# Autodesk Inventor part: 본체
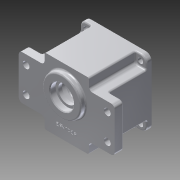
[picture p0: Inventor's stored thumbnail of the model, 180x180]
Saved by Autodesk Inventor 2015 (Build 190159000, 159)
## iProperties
Created: 2014-12
Part Number: 본체
Material: 알루미늄 6061
Document SubType Name: Modeling
Designer: 영환
Density: 2.7 g/cm^3
Appearance: 알루미늄 - 평지
Mass: 705.786 g
Surface Area: 673.294 cm^2
Volume: 261.402 cm^3
Author: 영환
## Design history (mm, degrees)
node "작업 평면1"
sketch "스케치1"
  geometry: L1 (45, -45)-(-45, -45); L2 (-45, -45)-(-45, 45); L3 (-45, 45)-(45, 45); L4 (45, 45)-(45, -45); L5 (45, -45)-(-45, 45); L6 (-45, -45)-(45, 45); 1 further point
  constraints: 12 end point, 2 midpoint, 2 parallel, 1 horizontal, 1 perpendicular
  dimensions: "d0" = 90 distance of L2.end L3.end; "d1" = 90 distance of L1.end L2.end
extrude "돌출1" new body sketch "스케치1" distance "d3" = 70; taper "d4" = 0 deg
sketch "스케치2"
  geometry: L1 (-65, 30)-(65, 30); L2 (65, 30)-(65, -30); L3 (65, -30)-(-65, -30); L4 (-65, -30)-(-65, 30); L5 (-65, 30)-(65, -30); L6 (65, 30)-(-65, -30); 1 further point
  constraints: 12 end point, 2 midpoint, 2 parallel, 1 horizontal, 1 perpendicular
  dimensions: "d5" = 130 distance of L2.end L3.end; "d6" = 60 distance of L1.end L2.end
extrude "돌출2" join sketch "스케치2" distance "d7" = 12; taper "d8" = 0 deg
sketch "스케치3"
  geometry: L1 (-45, -45)-(45, -45) reference; L2 (45, -45)-(45, -30) reference; L3 (45, 45)-(-45, 45) reference; L4 (-45, 45)-(-45, 30) reference; L5 (45, 45)-(30, 45); L6 (30, 45)-(30, 30); L7 (30, 30)-(45, 30); L8 (45, 30)-(45, 45); L9 (-45, 45)-(-45, 30); L10 (-45, 30)-(-30, 30); L11 (-30, 30)-(-30, 45); L12 (-30, 45)-(-45, 45); L13 (-45, -45)-(-30, -45); L14 (-30, -45)-(-30, -30); L15 (-30, -30)-(-45, -30); L16 (-45, -30)-(-45, -45); L17 (45, -45)-(45, -30); L18 (45, -30)-(30, -30); L19 (30, -30)-(30, -45); L20 (30, -45)-(45, -45); L21 (-45, -30)-(-45, -45) reference; L22 (65, -30)-(45, -30) reference; L23 (65, 30)-(65, -30) reference; L24 (45, 30)-(65, 30) reference; L25 (45, 30)-(45, 45) reference; L26 (-65, 30)-(-45, 30) reference; L27 (-65, -30)-(-65, 30) reference; L28 (-45, -30)-(-65, -30) reference; 1 further point
  constraints: 32 end point, 2 parallel, 1 horizontal, 1 perpendicular, 33 other
  dimensions: "d9" = 15 distance between parallel lines of L2 L6; "d10" = 15 distance of L5.end L6.end; "d13" = 360 deg dimension on point (0, 0) L6.end (derived)
extrude "돌출3" cut sketch "스케치3" distance "d15" = 63; taper "d16" = 0 deg
sketch "스케치4"
  geometry: 2 further points
  constraints: 1 coincident
hole "구멍1" sketch "스케치4" at (0, 0) diameter "d17" = 78; stored, may be unused: countersink angle "d21" = 90 deg, drill point angle "d23" = 0 deg; dims "d18" = 6, "d19" = 80, "d20" = 9, "d22" = 61
sketch "스케치5"
  geometry: L1 (-27.577, 21.92)-(-30.26, 24.603); L2 (-21.92, 27.577)-(-24.603, 30.26); L3 (-27.577, -21.92)-(-30.26, -24.603); L4 (-21.92, -27.577)-(-24.603, -30.26); L5 (21.92, -27.577)-(24.603, -30.26); L6 (27.577, -21.92)-(30.26, -24.603); L7 (27.577, 21.92)-(30.26, 24.603); L8 (21.92, 27.577)-(24.603, 30.26); C1 r 35 at (0, 0); A1 r 4 centre (-24.749, 24.749) between (-27.577, 21.92) and (-21.92, 27.577); A2 r 39 centre (0, 0) between (-24.603, 30.26) and (-30.26, 24.603); A3 r 4 centre (-24.749, -24.749) between (-21.92, -27.577) and (-27.577, -21.92); A4 r 39 centre (0, 0) between (-30.26, -24.603) and (-24.603, -30.26); A5 r 4 centre (24.749, -24.749) between (27.577, -21.92) and (21.92, -27.577); A6 r 39 centre (0, 0) between (24.603, -30.26) and (30.26, -24.603); A7 r 4 centre (24.749, 24.749) between (21.92, 27.577) and (27.577, 21.92); A8 r 39 centre (0, 0) between (30.26, 24.603) and (24.603, 30.26); 1 further point
  constraints: 16 end point, 16 point on circle, 9 centre point, 2 tangent, 1 coincident, 41 other
  dimensions: "d24" = 70 diameter of C1; "d25" = 8 diameter of A1; "d28" = 360 deg dimension on point (0, 0) A1.centre (derived)
extrude "돌출4" join sketch "스케치5" stored distance "d30" = 0; taper "d31" = 0 deg
sketch "스케치6"
  geometry: C1 r 20.5 at (0, -11); 2 further points
  constraints: 1 centre point, 1 coincident, 1 vertical alignment
  dimensions: "d33" = 41 diameter of C1; "d145" = 11 distance of point (0, -11) point (0, 0)
extrude "돌출5" join sketch "스케치6" distance "d34" = 7; taper "d35" = 0 deg
sketch "스케치7"
  geometry: C1 r 14 at (0, 20); 2 further points
  constraints: 1 centre point, 1 coincident, 1 vertical alignment
  dimensions: "d37" = 28 diameter of C1; "d146" = 20 distance of point (0, 0) C1.centre
extrude "돌출6" join sketch "스케치7" distance "d38" = 7; taper "d39" = 0 deg
sketch "스케치8"
  geometry: C1 r 26 at (0, 11); A1 r 20.5 centre (0, 11) between (7.402, -8.117) and (-7.402, -8.117) reference; 2 further points
  constraints: 2 coincident, 1 centre point
  dimensions: "d40" = 52 diameter of C1
extrude "돌출7" join sketch "스케치8" distance "d41" = 7; taper "d42" = 0 deg
sketch "스케치9"
  geometry: L1 (-55, 17.5)-(55, 17.5); L2 (55, 17.5)-(55, -17.5); L3 (55, -17.5)-(-55, -17.5); L4 (-55, -17.5)-(-55, 17.5); L5 (-55, 17.5)-(55, -17.5); L6 (55, 17.5)-(-55, -17.5); 5 further points
  constraints: 12 end point, 4 coincident, 2 midpoint, 2 parallel, 1 horizontal, 1 perpendicular
  dimensions: "d43" = 35 distance of L1.end L2.end; "d44" = 110 distance of L2.end L3.end
hole "구멍2" sketch "스케치9" at (-55, 17.5), (-55, -17.5), (55, -17.5), (55, 17.5) diameter "d45" = 9; stored, may be unused: countersink angle "d49" = 90 deg, drill point angle "d51" = 0 deg; dims "d46" = 6, "d47" = 80, "d48" = 9, "d50" = 61
sketch "스케치10"
  geometry: L1 (-37, 37)-(37, 37); L2 (37, 37)-(37, -37); L3 (37, -37)-(-37, -37); L4 (-37, -37)-(-37, 37); L5 (-37, 37)-(37, -37); L6 (37, 37)-(-37, -37); 5 further points
  constraints: 12 end point, 4 coincident, 2 midpoint, 2 parallel, 1 horizontal, 1 perpendicular
  dimensions: "d52" = 74 distance of L1.start L1.end; "d53" = 74 distance of L1.end L2.end
hole "구멍3" sketch "스케치10" at (-37, 37), (37, 37), (37, -37), (-37, -37) diameter "d54" = 7; stored, may be unused: countersink angle "d58" = 90 deg, drill point angle "d60" = 0 deg; dims "d55" = 6, "d56" = 80, "d57" = 9, "d59" = 61
hole "구멍4" diameter "d63" = 19; stored, may be unused: countersink angle "d67" = 90 deg, drill point angle "d69" = 0 deg; dims "d61" = 10, "d62" = 10, "d64" = 6, "d65" = 22, "d66" = 7, "d68" = 8
hole "구멍5" diameter "d72" = 25; stored, may be unused: countersink angle "d76" = 90 deg, drill point angle "d78" = 0 deg; dims "d70" = 10, "d71" = 10, "d73" = 6, "d74" = 35, "d75" = 10, "d77" = 8
hole "구멍6" diameter "d81" = 32; stored, may be unused: countersink angle "d85" = 90 deg, drill point angle "d87" = 0 deg; dims "d79" = 10, "d80" = 10, "d82" = 6, "d83" = 32, "d84" = 10, "d86" = 8
hole "구멍7" diameter "d90" = 3.459; stored, may be unused: countersink angle "d94" = 90 deg, drill point angle "d96" = 118 deg; dims "d91" = 12, "d92" = 32, "d93" = 10, "d95" = 15, "d124" = 10, "d125" = 10
hole "구멍8" diameter "d99" = 3.459; stored, may be unused: countersink angle "d103" = 90 deg, drill point angle "d105" = 118 deg; dims "d100" = 12, "d101" = 32, "d102" = 10, "d104" = 15, "d126" = 10, "d127" = 10
hole "구멍9" diameter "d108" = 3.459; stored, may be unused: countersink angle "d112" = 90 deg, drill point angle "d114" = 118 deg; dims "d109" = 12, "d110" = 32, "d111" = 10, "d113" = 15, "d128" = 10, "d129" = 10
hole "구멍10" diameter "d117" = 3.459; stored, may be unused: countersink angle "d121" = 90 deg, drill point angle "d123" = 118 deg; dims "d118" = 12, "d119" = 32, "d120" = 10, "d122" = 15, "d130" = 10, "d131" = 10
chamfer "모따기1" distance "d132" = 1; stored, may be unused: second distance "d133" = 2, angle "d134" = 45 deg
fillet "모깎기1" dims "d135" = 5
fillet "모깎기2" dims "d136" = 8
fillet "모깎기3" dims "d137" = 0.3
fillet "모깎기4" dims "d138" = 3.5
fillet "모깎기5" dims "d139" = 2
fillet "모깎기6" dims "d140" = 5
fillet "모깎기7" dims "d141" = 3
feature "엠보싱1" dims "d0" = 90, "d1" = 90, "d143" = 0.5, "d144" = 0
node "솔리드1"
sketch "스케치11"
  geometry: L1 (37, -45)-(-37, -45) reference; 2 further points
  constraints: 1 other
  dimensions: "d148" = 15 distance from line of point (0, -30) L1
node "투영된 루프1"
other parameters: "d2" = 7
